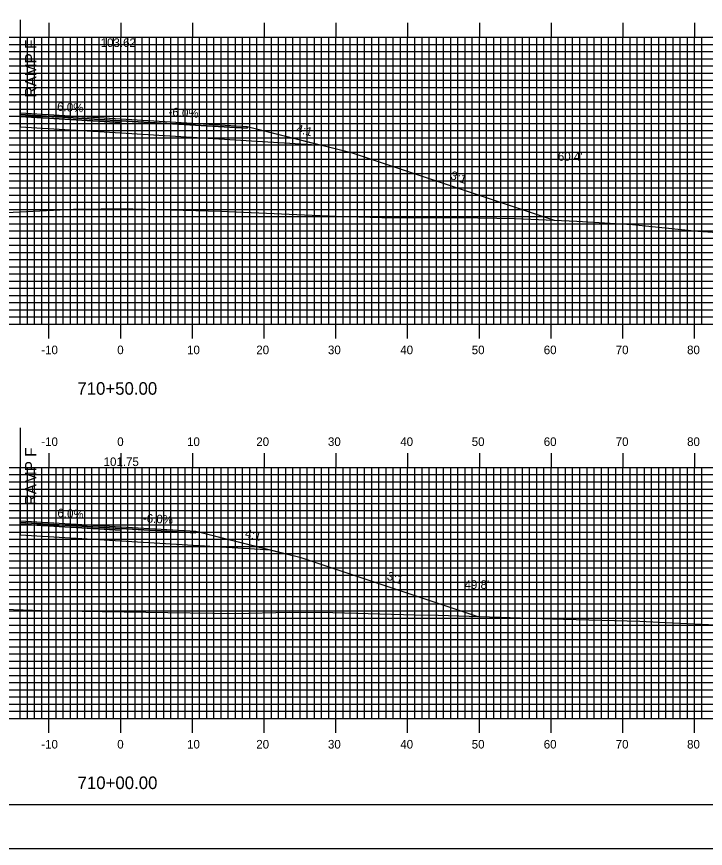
# Model space of a CAD drawing. Extents: x 854903 to 855247, y 364366 to 364586.
# Drawn here: x 855054.8 to 855150.8, y 364365.7 to 364481.7 of the extents above; entities that cross this region are included whole.
import ezdxf

# ---------------------------------------------------------------- set-up
doc = ezdxf.new("R2010")
doc.units = 0
for name, color, linetype in [('ANNOTATION', 7, 'Continuous'), ('BORDER', 7, 'Continuous'), ('D_Roadway_Centerline', 7, 'Continuous'), ('D_Roadway_Centerline_Text', 7, 'Continuous'), ('D_Roadway_Edge_Shoulder', 7, 'Continuous'), ('D_Roadway_Edge_TW', 7, 'Continuous'), ('D_Roadway_Pavement', 7, 'Continuous'), ('D_Roadway_SlopeLines', 7, 'Continuous'), ('D_Roadway_SubGrade', 7, 'Continuous'), ('D_Text_Standard', 7, 'Continuous'), ('H_V ANNOTATION', 7, 'Continuous'), ('MAJOR', 7, 'Continuous'), ('MINOR', 7, 'Continuous'), ('PLOT BOUNDARY', 7, 'Continuous'), ('S_Roadway_Centerline', 7, 'Continuous')]:
    doc.layers.add(name, color=color, linetype=linetype)

msp = doc.modelspace()

# ---------------------------------------------------------------- linework, layer by layer
at = {"layer": 'BORDER'}
msp.add_lwpolyline([(854919.66, 364371.79), (855239.66, 364371.79), (855239.66, 364581.79), (854919.66, 364581.79)], close=True, dxfattribs=at)
at = {"layer": 'D_Roadway_Centerline'}
for points in [[(855055.26, 364468.25), (855069.26, 364467.41), (855086.87, 364466.35), (855097.4, 364463.72)], [(855055.26, 364411.37), (855069.26, 364410.53), (855079.73, 364409.91), (855090.25, 364407.27), (855094.25, 364406.27), (855119.06, 364398.01)]]:
    msp.add_lwpolyline(points, dxfattribs=at)
at = {"layer": 'D_Roadway_Edge_Shoulder'}
for points in [[(855069.26, 364467.41), (855086.87, 364466.35), (855086.87, 364466.1), (855069.26, 364467.16)], [(855069.26, 364410.53), (855079.73, 364409.91), (855079.73, 364409.66), (855069.26, 364410.28)]]:
    msp.add_lwpolyline(points, close=True, dxfattribs=at)
at = {"layer": 'D_Roadway_Edge_TW'}
for points in [[(855055.26, 364468.25), (855069.26, 364467.41), (855069.26, 364467.16), (855055.26, 364468)], [(855055.26, 364411.37), (855069.26, 364410.53), (855069.26, 364410.28), (855055.26, 364411.12)]]:
    msp.add_lwpolyline(points, close=True, dxfattribs=at)
at = {"layer": 'D_Roadway_Pavement'}
for points in [[(855055.26, 364468), (855069.26, 364467.16), (855069.26, 364466.91), (855055.26, 364467.75)], [(855055.26, 364411.12), (855069.26, 364410.28), (855069.26, 364410.03), (855055.26, 364410.87)]]:
    msp.add_lwpolyline(points, close=True, dxfattribs=at)
for points in [[(855069.26, 364467.16), (855069.26, 364466.91)], [(855069.26, 364410.28), (855069.26, 364410.03)]]:
    msp.add_lwpolyline(points, dxfattribs=at)
at = {"layer": 'D_Roadway_SlopeLines'}
for points in [[(855086.87, 364466.35), (855101.4, 364462.72), (855129.66, 364453.3)], [(855079.73, 364409.91), (855094.25, 364406.27), (855119.06, 364398.01)]]:
    msp.add_lwpolyline(points, dxfattribs=at)
at = {"layer": 'D_Roadway_SubGrade'}
for p, q in [((855055.26, 364481.21), (855055.26, 364466.25)), ((855055.26, 364424.33), (855055.26, 364409.37))]:
    msp.add_line(p, q, dxfattribs=at)
for points in [[(855055.26, 364467.75), (855069.26, 364466.91), (855069.26, 364465.41), (855055.26, 364466.25)], [(855069.26, 364466.91), (855069.26, 364467.16), (855086.87, 364466.1), (855086.87, 364466.35), (855097.4, 364463.72), (855069.26, 364465.41)], [(855055.26, 364410.87), (855069.26, 364410.03), (855069.26, 364408.53), (855055.26, 364409.37)], [(855069.26, 364410.03), (855069.26, 364410.28), (855079.73, 364409.66), (855079.73, 364409.91), (855090.25, 364407.27), (855069.26, 364408.53)]]:
    msp.add_lwpolyline(points, close=True, dxfattribs=at)
at = {"layer": 'MAJOR'}
for p, q in [((855059.26, 364480.79), (855059.26, 364478.79)), ((855069.26, 364480.79), (855069.26, 364478.79)), ((855079.26, 364480.79), (855079.26, 364478.79)), ((855089.26, 364480.79), (855089.26, 364478.79)), ((855099.26, 364480.79), (855099.26, 364478.79)), ((855109.26, 364480.79), (855109.26, 364478.79)), ((855119.26, 364480.79), (855119.26, 364478.79)), ((855129.26, 364480.79), (855129.26, 364478.79)), ((855139.26, 364480.79), (855139.26, 364478.79)), ((855149.26, 364480.79), (855149.26, 364478.79)), ((854929.26, 364478.79), (855209.26, 364478.79)), ((854929.26, 364478.79), (855209.26, 364478.79)), ((855059.26, 364438.79), (855059.26, 364478.79)), ((855069.26, 364438.79), (855069.26, 364478.79)), ((855079.26, 364438.79), (855079.26, 364478.79)), ((855089.26, 364438.79), (855089.26, 364478.79)), ((855099.26, 364438.79), (855099.26, 364478.79)), ((855109.26, 364438.79), (855109.26, 364478.79)), ((855119.26, 364438.79), (855119.26, 364478.79)), ((855129.26, 364438.79), (855129.26, 364478.79)), ((855139.26, 364438.79), (855139.26, 364478.79)), ((855149.26, 364438.79), (855149.26, 364478.79)), ((854929.26, 364473.79), (855209.26, 364473.79)), ((854929.26, 364468.79), (855209.26, 364468.79)), ((854929.26, 364463.79), (855209.26, 364463.79)), ((854929.26, 364458.79), (855209.26, 364458.79)), ((854929.26, 364453.79), (855209.26, 364453.79)), ((854929.26, 364448.79), (855209.26, 364448.79)), ((854929.26, 364443.79), (855209.26, 364443.79)), ((854929.26, 364438.79), (855209.26, 364438.79)), ((854929.26, 364438.79), (855209.26, 364438.79)), ((855059.26, 364436.78), (855059.26, 364438.79)), ((855069.26, 364436.78), (855069.26, 364438.79)), ((855079.26, 364436.78), (855079.26, 364438.79)), ((855089.26, 364436.78), (855089.26, 364438.79)), ((855099.26, 364436.78), (855099.26, 364438.79)), ((855109.26, 364436.78), (855109.26, 364438.79)), ((855119.26, 364436.78), (855119.26, 364438.79)), ((855129.26, 364436.78), (855129.26, 364438.79)), ((855139.26, 364436.78), (855139.26, 364438.79)), ((855149.26, 364436.78), (855149.26, 364438.79)), ((855059.26, 364420.79), (855059.26, 364418.79)), ((855069.26, 364420.79), (855069.26, 364418.79)), ((855079.26, 364420.79), (855079.26, 364418.79)), ((855089.26, 364420.79), (855089.26, 364418.79)), ((855099.26, 364420.79), (855099.26, 364418.79)), ((855109.26, 364420.79), (855109.26, 364418.79)), ((855119.26, 364420.79), (855119.26, 364418.79)), ((855129.26, 364420.79), (855129.26, 364418.79)), ((855139.26, 364420.79), (855139.26, 364418.79)), ((855149.26, 364420.79), (855149.26, 364418.79)), ((854929.26, 364418.79), (855209.26, 364418.79)), ((854929.26, 364418.79), (855209.26, 364418.79)), ((855059.26, 364383.79), (855059.26, 364418.79)), ((855069.26, 364383.79), (855069.26, 364418.79)), ((855079.26, 364383.79), (855079.26, 364418.79)), ((855089.26, 364383.79), (855089.26, 364418.79)), ((855099.26, 364383.79), (855099.26, 364418.79)), ((855109.26, 364383.79), (855109.26, 364418.79)), ((855119.26, 364383.79), (855119.26, 364418.79)), ((855129.26, 364383.79), (855129.26, 364418.79)), ((855139.26, 364383.79), (855139.26, 364418.79)), ((855149.26, 364383.79), (855149.26, 364418.79)), ((854929.26, 364413.79), (855209.26, 364413.79)), ((854929.26, 364408.79), (855209.26, 364408.79)), ((854929.26, 364403.79), (855209.26, 364403.79)), ((854929.26, 364398.79), (855209.26, 364398.79)), ((854929.26, 364393.79), (855209.26, 364393.79)), ((854929.26, 364388.79), (855209.26, 364388.79)), ((854929.26, 364383.79), (855209.26, 364383.79)), ((854929.26, 364383.79), (855209.26, 364383.79)), ((855059.26, 364381.78), (855059.26, 364383.79)), ((855069.26, 364381.78), (855069.26, 364383.79)), ((855079.26, 364381.78), (855079.26, 364383.79)), ((855089.26, 364381.78), (855089.26, 364383.79)), ((855099.26, 364381.78), (855099.26, 364383.79)), ((855109.26, 364381.78), (855109.26, 364383.79)), ((855119.26, 364381.78), (855119.26, 364383.79)), ((855129.26, 364381.78), (855129.26, 364383.79)), ((855139.26, 364381.78), (855139.26, 364383.79)), ((855149.26, 364381.78), (855149.26, 364383.79))]:
    msp.add_line(p, q, dxfattribs=at)
at = {"layer": 'MINOR'}
for p, q in [((855055.26, 364438.79), (855055.26, 364478.79)), ((855056.26, 364438.79), (855056.26, 364478.79)), ((855057.26, 364438.79), (855057.26, 364478.79)), ((855058.26, 364438.79), (855058.26, 364478.79)), ((855060.26, 364438.79), (855060.26, 364478.79)), ((855061.26, 364438.79), (855061.26, 364478.79)), ((855062.26, 364438.79), (855062.26, 364478.79)), ((855063.26, 364438.79), (855063.26, 364478.79)), ((855064.26, 364438.79), (855064.26, 364478.79)), ((855065.26, 364438.79), (855065.26, 364478.79)), ((855066.26, 364438.79), (855066.26, 364478.79)), ((855067.26, 364438.79), (855067.26, 364478.79)), ((855068.26, 364438.79), (855068.26, 364478.79)), ((855070.26, 364438.79), (855070.26, 364478.79)), ((855071.26, 364438.79), (855071.26, 364478.79)), ((855072.26, 364438.79), (855072.26, 364478.79)), ((855073.26, 364438.79), (855073.26, 364478.79)), ((855074.26, 364438.79), (855074.26, 364478.79)), ((855075.26, 364438.79), (855075.26, 364478.79)), ((855076.26, 364438.79), (855076.26, 364478.79)), ((855077.26, 364438.79), (855077.26, 364478.79)), ((855078.26, 364438.79), (855078.26, 364478.79)), ((855080.26, 364438.79), (855080.26, 364478.79)), ((855081.26, 364438.79), (855081.26, 364478.79)), ((855082.26, 364438.79), (855082.26, 364478.79)), ((855083.26, 364438.79), (855083.26, 364478.79)), ((855084.26, 364438.79), (855084.26, 364478.79)), ((855085.26, 364438.79), (855085.26, 364478.79)), ((855086.26, 364438.79), (855086.26, 364478.79)), ((855087.26, 364438.79), (855087.26, 364478.79)), ((855088.26, 364438.79), (855088.26, 364478.79)), ((855090.26, 364438.79), (855090.26, 364478.79)), ((855091.26, 364438.79), (855091.26, 364478.79)), ((855092.26, 364438.79), (855092.26, 364478.79)), ((855093.26, 364438.79), (855093.26, 364478.79)), ((855094.26, 364438.79), (855094.26, 364478.79)), ((855095.26, 364438.79), (855095.26, 364478.79)), ((855096.26, 364438.79), (855096.26, 364478.79)), ((855097.26, 364438.79), (855097.26, 364478.79)), ((855098.26, 364438.79), (855098.26, 364478.79)), ((855100.26, 364438.79), (855100.26, 364478.79)), ((855101.26, 364438.79), (855101.26, 364478.79)), ((855102.26, 364438.79), (855102.26, 364478.79)), ((855103.26, 364438.79), (855103.26, 364478.79)), ((855104.26, 364438.79), (855104.26, 364478.79)), ((855105.26, 364438.79), (855105.26, 364478.79)), ((855106.26, 364438.79), (855106.26, 364478.79)), ((855107.26, 364438.79), (855107.26, 364478.79)), ((855108.26, 364438.79), (855108.26, 364478.79)), ((855110.26, 364438.79), (855110.26, 364478.79)), ((855111.26, 364438.79), (855111.26, 364478.79)), ((855112.26, 364438.79), (855112.26, 364478.79)), ((855113.26, 364438.79), (855113.26, 364478.79)), ((855114.26, 364438.79), (855114.26, 364478.79)), ((855115.26, 364438.79), (855115.26, 364478.79)), ((855116.26, 364438.79), (855116.26, 364478.79)), ((855117.26, 364438.79), (855117.26, 364478.79)), ((855118.26, 364438.79), (855118.26, 364478.79)), ((855120.26, 364438.79), (855120.26, 364478.79)), ((855121.26, 364438.79), (855121.26, 364478.79)), ((855122.26, 364438.79), (855122.26, 364478.79)), ((855123.26, 364438.79), (855123.26, 364478.79)), ((855124.26, 364438.79), (855124.26, 364478.79)), ((855125.26, 364438.79), (855125.26, 364478.79)), ((855126.26, 364438.79), (855126.26, 364478.79)), ((855127.26, 364438.79), (855127.26, 364478.79)), ((855128.26, 364438.79), (855128.26, 364478.79)), ((855130.26, 364438.79), (855130.26, 364478.79)), ((855131.26, 364438.79), (855131.26, 364478.79)), ((855132.26, 364438.79), (855132.26, 364478.79)), ((855133.26, 364438.79), (855133.26, 364478.79)), ((855134.26, 364438.79), (855134.26, 364478.79)), ((855135.26, 364438.79), (855135.26, 364478.79)), ((855136.26, 364438.79), (855136.26, 364478.79)), ((855137.26, 364438.79), (855137.26, 364478.79)), ((855138.26, 364438.79), (855138.26, 364478.79)), ((855140.26, 364438.79), (855140.26, 364478.79)), ((855141.26, 364438.79), (855141.26, 364478.79)), ((855142.26, 364438.79), (855142.26, 364478.79)), ((855143.26, 364438.79), (855143.26, 364478.79)), ((855144.26, 364438.79), (855144.26, 364478.79)), ((855145.26, 364438.79), (855145.26, 364478.79)), ((855146.26, 364438.79), (855146.26, 364478.79)), ((855147.26, 364438.79), (855147.26, 364478.79)), ((855148.26, 364438.79), (855148.26, 364478.79)), ((855150.26, 364438.79), (855150.26, 364478.79)), ((854929.26, 364477.79), (855209.26, 364477.79)), ((854929.26, 364476.79), (855209.26, 364476.79)), ((854929.26, 364475.79), (855209.26, 364475.79)), ((854929.26, 364474.79), (855209.26, 364474.79)), ((854929.26, 364472.79), (855209.26, 364472.79)), ((854929.26, 364471.79), (855209.26, 364471.79)), ((854929.26, 364470.79), (855209.26, 364470.79)), ((854929.26, 364469.79), (855209.26, 364469.79)), ((854929.26, 364467.79), (855209.26, 364467.79)), ((854929.26, 364466.79), (855209.26, 364466.79)), ((854929.26, 364465.79), (855209.26, 364465.79)), ((854929.26, 364464.79), (855209.26, 364464.79)), ((854929.26, 364462.79), (855209.26, 364462.79)), ((854929.26, 364461.79), (855209.26, 364461.79)), ((854929.26, 364460.79), (855209.26, 364460.79)), ((854929.26, 364459.79), (855209.26, 364459.79)), ((854929.26, 364457.79), (855209.26, 364457.79)), ((854929.26, 364456.79), (855209.26, 364456.79)), ((854929.26, 364455.79), (855209.26, 364455.79)), ((854929.26, 364454.79), (855209.26, 364454.79)), ((854929.26, 364452.79), (855209.26, 364452.79)), ((854929.26, 364451.79), (855209.26, 364451.79)), ((854929.26, 364450.79), (855209.26, 364450.79)), ((854929.26, 364449.79), (855209.26, 364449.79)), ((854929.26, 364447.79), (855209.26, 364447.79)), ((854929.26, 364446.79), (855209.26, 364446.79)), ((854929.26, 364445.79), (855209.26, 364445.79)), ((854929.26, 364444.79), (855209.26, 364444.79)), ((854929.26, 364442.79), (855209.26, 364442.79)), ((854929.26, 364441.79), (855209.26, 364441.79)), ((854929.26, 364440.79), (855209.26, 364440.79)), ((854929.26, 364439.79), (855209.26, 364439.79)), ((854929.26, 364417.79), (855209.26, 364417.79)), ((855055.26, 364383.79), (855055.26, 364418.79)), ((855056.26, 364383.79), (855056.26, 364418.79)), ((855057.26, 364383.79), (855057.26, 364418.79)), ((855058.26, 364383.79), (855058.26, 364418.79)), ((855060.26, 364383.79), (855060.26, 364418.79)), ((855061.26, 364383.79), (855061.26, 364418.79)), ((855062.26, 364383.79), (855062.26, 364418.79)), ((855063.26, 364383.79), (855063.26, 364418.79)), ((855064.26, 364383.79), (855064.26, 364418.79)), ((855065.26, 364383.79), (855065.26, 364418.79)), ((855066.26, 364383.79), (855066.26, 364418.79)), ((855067.26, 364383.79), (855067.26, 364418.79)), ((855068.26, 364383.79), (855068.26, 364418.79)), ((855070.26, 364383.79), (855070.26, 364418.79)), ((855071.26, 364383.79), (855071.26, 364418.79)), ((855072.26, 364383.79), (855072.26, 364418.79)), ((855073.26, 364383.79), (855073.26, 364418.79)), ((855074.26, 364383.79), (855074.26, 364418.79)), ((855075.26, 364383.79), (855075.26, 364418.79)), ((855076.26, 364383.79), (855076.26, 364418.79)), ((855077.26, 364383.79), (855077.26, 364418.79)), ((855078.26, 364383.79), (855078.26, 364418.79)), ((855080.26, 364383.79), (855080.26, 364418.79)), ((855081.26, 364383.79), (855081.26, 364418.79)), ((855082.26, 364383.79), (855082.26, 364418.79)), ((855083.26, 364383.79), (855083.26, 364418.79)), ((855084.26, 364383.79), (855084.26, 364418.79)), ((855085.26, 364383.79), (855085.26, 364418.79)), ((855086.26, 364383.79), (855086.26, 364418.79)), ((855087.26, 364383.79), (855087.26, 364418.79)), ((855088.26, 364383.79), (855088.26, 364418.79)), ((855090.26, 364383.79), (855090.26, 364418.79)), ((855091.26, 364383.79), (855091.26, 364418.79)), ((855092.26, 364383.79), (855092.26, 364418.79)), ((855093.26, 364383.79), (855093.26, 364418.79)), ((855094.26, 364383.79), (855094.26, 364418.79)), ((855095.26, 364383.79), (855095.26, 364418.79)), ((855096.26, 364383.79), (855096.26, 364418.79)), ((855097.26, 364383.79), (855097.26, 364418.79)), ((855098.26, 364383.79), (855098.26, 364418.79)), ((855100.26, 364383.79), (855100.26, 364418.79)), ((855101.26, 364383.79), (855101.26, 364418.79)), ((855102.26, 364383.79), (855102.26, 364418.79)), ((855103.26, 364383.79), (855103.26, 364418.79)), ((855104.26, 364383.79), (855104.26, 364418.79)), ((855105.26, 364383.79), (855105.26, 364418.79)), ((855106.26, 364383.79), (855106.26, 364418.79)), ((855107.26, 364383.79), (855107.26, 364418.79)), ((855108.26, 364383.79), (855108.26, 364418.79)), ((855110.26, 364383.79), (855110.26, 364418.79)), ((855111.26, 364383.79), (855111.26, 364418.79)), ((855112.26, 364383.79), (855112.26, 364418.79)), ((855113.26, 364383.79), (855113.26, 364418.79)), ((855114.26, 364383.79), (855114.26, 364418.79)), ((855115.26, 364383.79), (855115.26, 364418.79)), ((855116.26, 364383.79), (855116.26, 364418.79)), ((855117.26, 364383.79), (855117.26, 364418.79)), ((855118.26, 364383.79), (855118.26, 364418.79)), ((855120.26, 364383.79), (855120.26, 364418.79)), ((855121.26, 364383.79), (855121.26, 364418.79)), ((855122.26, 364383.79), (855122.26, 364418.79)), ((855123.26, 364383.79), (855123.26, 364418.79)), ((855124.26, 364383.79), (855124.26, 364418.79)), ((855125.26, 364383.79), (855125.26, 364418.79)), ((855126.26, 364383.79), (855126.26, 364418.79)), ((855127.26, 364383.79), (855127.26, 364418.79)), ((855128.26, 364383.79), (855128.26, 364418.79)), ((855130.26, 364383.79), (855130.26, 364418.79)), ((855131.26, 364383.79), (855131.26, 364418.79)), ((855132.26, 364383.79), (855132.26, 364418.79)), ((855133.26, 364383.79), (855133.26, 364418.79)), ((855134.26, 364383.79), (855134.26, 364418.79)), ((855135.26, 364383.79), (855135.26, 364418.79)), ((855136.26, 364383.79), (855136.26, 364418.79)), ((855137.26, 364383.79), (855137.26, 364418.79)), ((855138.26, 364383.79), (855138.26, 364418.79)), ((855140.26, 364383.79), (855140.26, 364418.79)), ((855141.26, 364383.79), (855141.26, 364418.79)), ((855142.26, 364383.79), (855142.26, 364418.79)), ((855143.26, 364383.79), (855143.26, 364418.79)), ((855144.26, 364383.79), (855144.26, 364418.79)), ((855145.26, 364383.79), (855145.26, 364418.79)), ((855146.26, 364383.79), (855146.26, 364418.79)), ((855147.26, 364383.79), (855147.26, 364418.79)), ((855148.26, 364383.79), (855148.26, 364418.79)), ((855150.26, 364383.79), (855150.26, 364418.79)), ((854929.26, 364416.79), (855209.26, 364416.79)), ((854929.26, 364415.79), (855209.26, 364415.79)), ((854929.26, 364414.79), (855209.26, 364414.79)), ((854929.26, 364412.79), (855209.26, 364412.79)), ((854929.26, 364411.79), (855209.26, 364411.79)), ((854929.26, 364410.79), (855209.26, 364410.79)), ((854929.26, 364409.79), (855209.26, 364409.79)), ((854929.26, 364407.79), (855209.26, 364407.79)), ((854929.26, 364406.79), (855209.26, 364406.79)), ((854929.26, 364405.79), (855209.26, 364405.79)), ((854929.26, 364404.79), (855209.26, 364404.79)), ((854929.26, 364402.79), (855209.26, 364402.79)), ((854929.26, 364401.79), (855209.26, 364401.79)), ((854929.26, 364400.79), (855209.26, 364400.79)), ((854929.26, 364399.79), (855209.26, 364399.79)), ((854929.26, 364397.79), (855209.26, 364397.79)), ((854929.26, 364396.79), (855209.26, 364396.79)), ((854929.26, 364395.79), (855209.26, 364395.79)), ((854929.26, 364394.79), (855209.26, 364394.79)), ((854929.26, 364392.79), (855209.26, 364392.79)), ((854929.26, 364391.79), (855209.26, 364391.79)), ((854929.26, 364390.79), (855209.26, 364390.79)), ((854929.26, 364389.79), (855209.26, 364389.79)), ((854929.26, 364387.79), (855209.26, 364387.79)), ((854929.26, 364386.79), (855209.26, 364386.79)), ((854929.26, 364385.79), (855209.26, 364385.79)), ((854929.26, 364384.79), (855209.26, 364384.79))]:
    msp.add_line(p, q, dxfattribs=at)
at = {"layer": 'PLOT BOUNDARY'}
msp.add_lwpolyline([(854903.47, 364365.67), (855243.47, 364365.67), (855243.47, 364585.67), (854903.47, 364585.67)], close=True, dxfattribs=at)
at = {"layer": 'S_Roadway_Centerline'}
for points in [[(855049.55, 364454.18), (855062.67, 364454.82), (855066.55, 364454.86), (855070.93, 364454.85), (855083.24, 364454.52), (855093.81, 364454.09), (855099.2, 364453.86), (855105.68, 364453.68), (855116.43, 364453.65), (855124.27, 364453.53), (855132.86, 364453.16), (855140.6, 364452.69), (855149.71, 364451.76), (855155.88, 364451.34), (855165.66, 364450.59), (855171.63, 364450.07), (855182.67, 364449.57), (855187.18, 364449.24), (855198.56, 364448.34), (855209.26, 364448.06)], [(855048.97, 364399.15), (855058.3, 364398.86), (855066.68, 364398.7), (855075.83, 364398.57), (855085.24, 364398.44), (855092.79, 364398.61), (855098.85, 364398.55), (855110.33, 364398.24), (855113.52, 364398.19), (855126.41, 364397.76), (855130.99, 364397.62), (855141.61, 364397.34), (855144.31, 364397.2), (855155.12, 364396.69), (855160.47, 364396.42), (855169.72, 364395.61), (855177.17, 364395.06), (855182.3, 364394.69), (855194.62, 364393.74), (855208.41, 364392.74), (855209.26, 364392.68)]]:
    msp.add_lwpolyline(points, dxfattribs=at)

# ---------------------------------------------------------------- texts
at = {"layer": 'ANNOTATION'}
for s, height, rotation, p in [('RAMP F', 1.6, 90, (855057.52, 364470.39)), ('6.0%', 1.2, 356.5664, (855060.37, 364468.55)), ('-6.0%', 1.2, 356.5664, (855075.9, 364467.81)), ('4:1', 1.2, 345.9638, (855093.64, 364465.52)), ('3:1', 1.2, 341.5652, (855115.13, 364459.05)), ('RAMP F', 1.6, 90, (855057.52, 364413.51)), ('6.0%', 1.2, 356.5664, (855060.41, 364411.87)), ('-6.0%', 1.2, 356.5664, (855072.33, 364411.15)), ('4:1', 1.2, 345.9638, (855086.5, 364409.08)), ('3:1', 1.2, 341.5652, (855106.26, 364403.18))]:
    msp.add_text(s, height=height, rotation=rotation, dxfattribs=at).set_placement(p)
at = {"layer": 'D_Roadway_Centerline_Text'}
for s, p in [('103.62', (855066.47, 364477.44)), ('101.75', (855066.88, 364418.99))]:
    msp.add_text(s, height=1.2, dxfattribs=at).set_placement(p)
at = {"layer": 'D_Text_Standard'}
for s, p in [("60.4'", (855130.2, 364461.57)), ("49.8'", (855117.19, 364401.86))]:
    msp.add_text(s, height=1.2, dxfattribs=at).set_placement(p)
at = {"layer": 'H_V ANNOTATION'}
for s, height, p in [('-10', 1.2, (855058.19, 364434.59)), ('0', 1.2, (855068.78, 364434.59)), ('10', 1.2, (855078.51, 364434.59)), ('20', 1.2, (855088.16, 364434.59)), ('30', 1.2, (855098.15, 364434.59)), ('40', 1.2, (855108.23, 364434.59)), ('50', 1.2, (855118.19, 364434.59)), ('60', 1.2, (855128.23, 364434.59)), ('70', 1.2, (855138.26, 364434.59)), ('80', 1.2, (855148.21, 364434.59)), ('710+50.00', 1.75, (855063.22, 364428.94)), ('-10', 1.2, (855058.19, 364421.79)), ('0', 1.2, (855068.78, 364421.79)), ('10', 1.2, (855078.51, 364421.79)), ('20', 1.2, (855088.16, 364421.79)), ('30', 1.2, (855098.15, 364421.79)), ('40', 1.2, (855108.23, 364421.79)), ('50', 1.2, (855118.19, 364421.79)), ('60', 1.2, (855128.23, 364421.79)), ('70', 1.2, (855138.26, 364421.79)), ('80', 1.2, (855148.21, 364421.79)), ('-10', 1.2, (855058.19, 364379.59)), ('0', 1.2, (855068.78, 364379.59)), ('10', 1.2, (855078.51, 364379.59)), ('20', 1.2, (855088.16, 364379.59)), ('30', 1.2, (855098.15, 364379.59)), ('40', 1.2, (855108.23, 364379.59)), ('50', 1.2, (855118.19, 364379.59)), ('60', 1.2, (855128.23, 364379.59)), ('70', 1.2, (855138.26, 364379.59)), ('80', 1.2, (855148.21, 364379.59)), ('710+00.00', 1.75, (855063.25, 364373.94))]:
    msp.add_text(s, height=height, dxfattribs=at).set_placement(p)

doc.saveas('drawing.dxf')
